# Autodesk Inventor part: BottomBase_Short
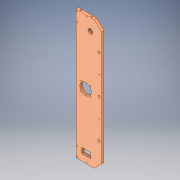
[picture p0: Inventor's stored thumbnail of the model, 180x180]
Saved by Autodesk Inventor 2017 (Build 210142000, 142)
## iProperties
Created: 2017-04
Part Number: BottomBase_Short
Material: Generic
Document SubType Name: Modeling
Designer: John
Density: 1 g/cm^3
Appearance: Default
Author: jledden
Sending System: NX 10.0.2.6
NX_MaterialMissingAssignments: TRUE
NX_MaterialMultipleAssigned: FALSE
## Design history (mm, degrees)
feature "SOLID1"
body "Solid1"
